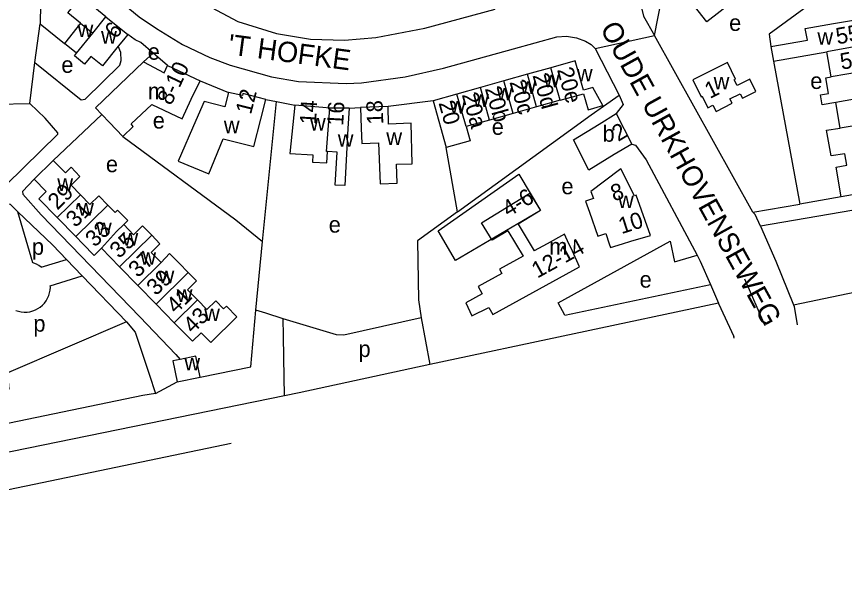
# Model space of a CAD drawing. Extents: x 162883 to 165538, y 383986 to 385172.
# Drawn here: x 164085 to 164288.3, y 384167.4 to 384305.7 of the extents above; entities that cross this region are included whole.
import ezdxf

# ---------------------------------------------------------------- set-up
doc = ezdxf.new("R2010")
doc.units = 0
for name, color, linetype in [('BLT_Basislijn', 7, 'Continuous'), ('BLT_Bebouwing', 7, 'Continuous'), ('BLT_Centroide', 7, 'Continuous'), ('BLT_Huisnummer', 7, 'Continuous'), ('BLT_Huisnummer_ tussenligend', 7, 'Continuous'), ('BLT_Huisnummer_reeks', 7, 'Continuous'), ('BLT_Huisnummer_zonder_bebouwing', 7, 'Continuous'), ('BLT_Onderverdeling_panden', 7, 'Continuous'), ('BLT_Plantopo', 7, 'Continuous'), ('BLT_Spoorlijn', 7, 'Continuous'), ('BLT_Straatnaam', 7, 'Continuous'), ('BLT_Vlakafsluiter', 7, 'Continuous')]:
    doc.layers.add(name, color=color, linetype=linetype)

msp = doc.modelspace()

# ---------------------------------------------------------------- linework, layer by layer
at = {"layer": 'BLT_Basislijn'}
for p, q in [((164106.92, 384305.67), (164100.86, 384310.64)), ((164227.04, 384297.9), (164232.93, 384286.41)), ((164116.19, 384294.57), (164118.57, 384296.7)), ((164122.09, 384293.71), (164118.57, 384296.7)), ((164088.28, 384284.4), (164089.52, 384294.46)), ((164270.83, 384294.78), (164277.3, 384259.69)), ((164130.06, 384289.94), (164137.05, 384287.05)), ((164145.39, 384250.53), (164148.81, 384284.87)), ((164146.25, 384285.35), (164148.81, 384284.87)), ((164148.81, 384284.87), (164153.33, 384284.01)), ((164187.26, 384285.05), (164176.21, 384283.66)), ((164228.98, 384283.9), (164229.11, 384283.72)), ((164166.66, 384283.26), (164169.47, 384283.4)), ((164193.24, 384257.84), (164190.48, 384273.56)), ((164287.5, 384261.53), (164277.3, 384259.69)), ((164265.79, 384257.69), (164277.3, 384259.69)), ((164085.28, 384257.93), (164088.92, 384245.35)), ((164143.72, 384233.7), (164145.39, 384250.53)), ((164217.96, 384235.51), (164245.48, 384250.58)), ((164091.06, 384244.2), (164097.26, 384246.14)), ((164101.13, 384242.11), (164097.26, 384246.14)), ((164093.3, 384239.66), (164101.13, 384242.11)), ((164111.98, 384230.83), (164101.13, 384242.11)), ((164263.74, 384241.37), (164268.73, 384229.94)), ((164219.62, 384232.49), (164255.36, 384240.01)), ((164255.36, 384240.01), (164257.34, 384235.42)), ((164257.34, 384235.42), (164186.45, 384220.4)), ((164219.62, 384232.49), (164217.96, 384235.51)), ((164257.34, 384235.42), (164257.38, 384235.32)), ((164257.38, 384235.32), (164261.11, 384227.25)), ((164146.18, 384232.94), (164143.72, 384233.7)), ((164150.5, 384231.6), (164146.18, 384232.94)), ((164115.27, 384232.08), (164124.08, 384222.79)), ((164150.57, 384227.48), (164150.5, 384231.6)), ((164184.38, 384231.82), (164186.45, 384220.4)), ((164150.67, 384221.99), (164150.57, 384227.48)), ((164261.22, 384226.85), (164261.11, 384227.25)), ((164124.08, 384222.79), (164125.18, 384221.63)), ((164150.83, 384212.71), (164150.67, 384221.99)), ((164186.45, 384220.4), (164154.38, 384213.43)), ((164117.54, 384218), (164119.14, 384213.22)), ((164119.14, 384213.22), (164124.48, 384216.09)), ((164150.83, 384212.71), (163969.22, 384175.66)), ((164119.14, 384213.22), (164116.02, 384212.73)), ((164154.38, 384213.43), (164150.83, 384212.71))]:
    msp.add_line(p, q, dxfattribs=at)
for points in [[(164300.18, 384395.02), (164295.59, 384393.9), (164294.19, 384393.19), (164293.14, 384391.74), (164290.67, 384383.96), (164285.39, 384371.56), (164279.22, 384361.24), (164270.12, 384349.98), (164261.4, 384340.32), (164243.74, 384320.55), (164240.78, 384317.34), (164238.38, 384313.16), (164237.93, 384309.92), (164238.95, 384305.82), (164241.62, 384301.03)], [(164241.62, 384301.03), (164244.24, 384314.47), (164264.79, 384333.93), (164268.2, 384336.97), (164268.52, 384337.22)], [(164090.13, 384329.25), (164104.56, 384315.21), (164110.51, 384309.41), (164115.15, 384305.64), (164119.37, 384302.75), (164125.75, 384298.85), (164132.5, 384295.63), (164137.45, 384293.75), (164147.6, 384290.92), (164154.24, 384289.8), (164165.92, 384289.31), (164169.7, 384289.49), (164180.44, 384290.95), (164189.84, 384293.02), (164207.02, 384297.8), (164217.62, 384300.75), (164220.05, 384300.9), (164222.45, 384300.52), (164224.73, 384299.68), (164226.1, 384298.88), (164227.04, 384297.9)], [(164122.73, 384313.37), (164139.36, 384304.46), (164148.85, 384301.52), (164157.22, 384300.19), (164165.56, 384299.88), (164173.22, 384300.54), (164185.25, 384302.84), (164202.51, 384307.56)], [(164286.77, 384313.86), (164269.82, 384301.39), (164270.2, 384298.36)], [(164089.52, 384294.46), (164090.81, 384303.95)], [(164118.57, 384296.7), (164115.49, 384299.31), (164114.11, 384300), (164112.32, 384301.34)], [(164265.79, 384257.69), (164241.62, 384301.03)], [(164089.52, 384294.46), (164100.84, 384285.29), (164101.86, 384285.45), (164110.41, 384293.77), (164110.72, 384294.94), (164110.6, 384296.92), (164109.99, 384298.43)], [(164537.04, 384298.36), (164444.4, 384281.69), (164443.92, 384281.32), (164443.78, 384279.5), (164414.83, 384274.17), (164413.46, 384274.09), (164412.69, 384277.13), (164412.28, 384277.16), (164358.24, 384267.65), (164355.83, 384267.19), (164355.01, 384265.8), (164304.07, 384256.84), (164302.9, 384256.99), (164302.04, 384260.09), (164301.53, 384260.09), (164267.64, 384254.3)], [(164229.11, 384283.72), (164232.93, 384286.41)], [(164232.93, 384286.41), (164233.96, 384284.12), (164232.26, 384281.94)], [(164061.09, 384244.88), (164062.5, 384245.17), (164065.53, 384247.95), (164095.17, 384276.86), (164095.17, 384277.18), (164092.06, 384280.8), (164088.28, 384284.4)], [(164063.93, 384283.89), (164088.28, 384284.4)], [(164193.24, 384257.84), (164226.1, 384281.59), (164229.11, 384283.72)], [(164105.92, 384281.72), (164094.03, 384270.44)], [(164111.11, 384276.28), (164138.84, 384255.85), (164145.39, 384250.53)], [(164236.06, 384274.4), (164236.95, 384274.14), (164239.55, 384270.6), (164252.11, 384247.18)], [(164089.3, 384265.81), (164086.5, 384262.83), (164086.57, 384262.17), (164091.1, 384257.07), (164115.27, 384232.08)], [(164085.28, 384257.93), (164083.53, 384259.61), (164083.1, 384259.67), (164080.34, 384257.01)], [(164097.26, 384246.14), (164093.89, 384249.64), (164085.28, 384257.93)], [(164193.24, 384257.84), (164183.45, 384250.66), (164183.73, 384236.23), (164184.38, 384231.82)], [(164267.64, 384254.3), (164266.32, 384257.12), (164265.79, 384257.69)], [(164267.64, 384254.3), (164271.43, 384245.69), (164275.8, 384234.96)], [(164245.48, 384250.58), (164246.54, 384245.55), (164252.11, 384247.18)], [(164252.11, 384247.18), (164252.88, 384245.74), (164255.36, 384240.01)], [(164275.8, 384234.96), (164298.55, 384239.75), (164300.69, 384243.25), (164327.24, 384248.79)], [(164091.06, 384244.2), (164090.49, 384244.61), (164089.88, 384244.97), (164089.24, 384245.25), (164088.92, 384245.35)], [(164084.83, 384233.62), (164085.5, 384233.41), (164086.19, 384233.26), (164086.9, 384233.2), (164087.6, 384233.22), (164088.3, 384233.32), (164088.98, 384233.49), (164089.64, 384233.74), (164090.26, 384234.07), (164090.85, 384234.46), (164091.39, 384234.92), (164091.87, 384235.43), (164092.29, 384236), (164092.64, 384236.61), (164092.92, 384237.26), (164093.13, 384237.93), (164093.26, 384238.62), (164093.31, 384239.33), (164093.3, 384239.66)], [(164275.8, 384234.96), (164275.89, 384234.62), (164276.69, 384230.09)], [(164130.1, 384217.27), (164142.51, 384219.77), (164143.72, 384233.7)], [(164111.98, 384230.83), (164083.06, 384218.41), (164082.81, 384218.06), (164083.09, 384214.28), (164082.86, 384214.12), (164071.11, 384211.55)], [(164111.98, 384230.83), (164114.1, 384228.32), (164117.54, 384218)], [(164184.38, 384231.82), (164165.35, 384227.52), (164163.59, 384227.68), (164150.5, 384231.6)], [(164116.02, 384212.73), (163993.66, 384187.45), (163993.19, 384187.45), (163960.99, 384219.5)]]:
    msp.add_lwpolyline(points, dxfattribs=at)
at = {"layer": 'BLT_Bebouwing'}
for p, q in [((164106.92, 384305.67), (164112.32, 384301.34)), ((164270.2, 384298.36), (164270.83, 384294.78)), ((164270.83, 384294.78), (164283.93, 384297.09)), ((164285.02, 384290.91), (164283.93, 384297.09)), ((164122.09, 384293.71), (164130.06, 384289.94)), ((164216.21, 384293.16), (164210.44, 384291.54)), ((164204.67, 384289.93), (164198.9, 384288.31)), ((164210.44, 384291.54), (164204.67, 384289.93)), ((164198.9, 384288.31), (164193.12, 384286.7)), ((164137.05, 384287.05), (164136.15, 384283.55)), ((164193.12, 384286.7), (164187.26, 384285.05)), ((164176.21, 384283.66), (164169.47, 384283.4)), ((164218.45, 384285.18), (164212.68, 384283.56)), ((164287.25, 384278.33), (164286.14, 384284.62)), ((164206.9, 384281.95), (164201.13, 384280.33)), ((164212.68, 384283.56), (164206.9, 384281.95)), ((164232.26, 384281.94), (164236.06, 384274.4)), ((164201.13, 384280.33), (164195.36, 384278.72)), ((164297.47, 384263.31), (164287.5, 384261.53)), ((164099.53, 384251.76), (164095.01, 384256.39)), ((164205.59, 384253.18), (164209.37, 384246.92)), ((164208.13, 384254.77), (164212.07, 384248.25)), ((164110.31, 384244.32), (164105.84, 384248.89)), ((164114.79, 384239.76), (164110.31, 384244.32)), ((164119.26, 384235.19), (164114.79, 384239.76)), ((164123.74, 384230.62), (164119.26, 384235.19)), ((164124.48, 384216.09), (164130.1, 384217.27))]:
    msp.add_line(p, q, dxfattribs=at)
for points in [[(164277.83, 384325.11), (164269.13, 384318.33), (164271.02, 384315.9), (164265.69, 384311.75), (164265.02, 384312.62), (164261.77, 384310.1), (164254.48, 384304.42), (164251.46, 384308.28), (164262.09, 384316.57), (164258.05, 384321.75), (164271.95, 384332.65)], [(164091.09, 384318.57), (164090.99, 384313.57), (164090.81, 384303.95)], [(164100.71, 384304.09), (164097.58, 384306.63), (164100.86, 384310.64)], [(164090.81, 384303.95), (164096.82, 384299.08)], [(164100.71, 384304.09), (164103.71, 384301.67)], [(164103.71, 384301.67), (164106.92, 384305.67)], [(164270.2, 384298.36), (164279.16, 384299.94), (164278.66, 384302.78), (164285.54, 384303.97), (164290.46, 384304.84), (164290.6, 384304.05), (164291.7, 384304.25), (164292.27, 384301.07), (164291.16, 384300.88), (164291.59, 384298.45)], [(164112.32, 384301.34), (164111.25, 384300), (164109.99, 384298.43)], [(164099.74, 384296.72), (164096.82, 384299.08)], [(164109.99, 384298.43), (164106.12, 384293.61), (164103.23, 384295.93), (164101.73, 384294.05), (164099.22, 384296.07), (164099.74, 384296.72)], [(164116.19, 384294.57), (164104.4, 384283.32), (164105.92, 384281.72)], [(164116.19, 384294.57), (164121.22, 384291.88), (164122.09, 384293.71)], [(164228.98, 384283.9), (164226.51, 384288.3), (164224.17, 384287.65), (164222.16, 384294.83), (164216.21, 384293.16)], [(164260.72, 384284.43), (164260.17, 384285.54), (164262.66, 384286.78), (164263.21, 384285.67), (164266.54, 384287.33), (164265.03, 384290.37), (164261.89, 384288.81), (164261.2, 384290.2), (164261.56, 384290.38), (164259.56, 384294.4), (164255.48, 384292.37), (164251.01, 384290.15), (164253.06, 384286.03), (164253.35, 384286.18), (164254.75, 384283.35), (164255.99, 384283.97), (164256.75, 384282.45), (164260.72, 384284.43)], [(164111.11, 384276.28), (164113.66, 384278.71), (164113.19, 384279.39), (164118.19, 384284.16), (164125.65, 384280.63), (164127.92, 384285.42), (164130.06, 384289.94)], [(164286.14, 384284.62), (164282.78, 384284.07), (164282.36, 384286.49), (164284.37, 384286.85), (164283.69, 384290.64), (164285.02, 384290.91)], [(164146.25, 384285.35), (164140.6, 384286.8), (164140.49, 384286.37), (164137.05, 384287.05)], [(164218.45, 384285.18), (164224.22, 384286.79), (164225.31, 384282.87), (164228.98, 384283.9)], [(164136.15, 384283.55), (164131.05, 384284.85), (164129.04, 384280.2), (164124.72, 384270.24), (164132.19, 384267.15), (164135.76, 384275.75)], [(164135.76, 384275.75), (164143.3, 384273.82), (164145.01, 384280.51), (164146.25, 384285.35)], [(164153.33, 384284.01), (164152.13, 384272.1), (164157.76, 384271.78), (164157.66, 384270.01), (164161.23, 384269.81), (164161.38, 384272.6)], [(164161.96, 384283.22), (164160.25, 384283.42), (164153.33, 384284.01)], [(164169.47, 384283.4), (164169.66, 384278.36), (164169.81, 384274.59), (164173.91, 384274.75), (164174.31, 384264.68), (164178.42, 384264.85), (164178.33, 384269.52), (164182.13, 384269.58), (164181.89, 384279.53), (164176.37, 384279.32), (164176.21, 384283.66)], [(164187.26, 384285.05), (164190.48, 384273.56)], [(164105.92, 384281.72), (164107.85, 384279.7), (164111.11, 384276.28)], [(164166.66, 384283.26), (164166.38, 384278.24), (164165.59, 384264.26), (164163.26, 384264.39), (164163.71, 384272.47), (164161.38, 384272.6)], [(164166.66, 384283.26), (164166.45, 384283.24), (164161.96, 384283.22)], [(164236.06, 384274.4), (164231.77, 384271.84), (164225.48, 384268.07), (164221.77, 384275.46), (164228.01, 384279.3), (164232.26, 384281.94)], [(164195.36, 384278.72), (164196.35, 384275.2), (164190.48, 384273.56)], [(164288.36, 384272.04), (164285, 384271.51), (164283.89, 384277.81), (164287.25, 384278.33)], [(164287.5, 384261.53), (164286.22, 384268.78), (164288.86, 384269.24), (164288.61, 384270.67), (164288.36, 384272.04)], [(164089.3, 384265.81), (164094.03, 384270.44)], [(164094.03, 384270.44), (164097.01, 384267.39), (164098.39, 384268.74), (164100.57, 384266.51), (164098.39, 384264.39), (164100.74, 384261.99)], [(164225.65, 384257.75), (164227.74, 384251.83), (164229.65, 384252.5), (164230.53, 384250), (164230.86, 384249.06), (164233.75, 384250), (164235.85, 384250.62), (164240.65, 384252.04), (164237.17, 384261.91), (164236.73, 384261.76), (164233.35, 384268.32), (164229.36, 384265.31), (164226.04, 384262.81), (164226.65, 384261.09), (164224.72, 384260.41), (164225.65, 384257.75)], [(164095.01, 384256.39), (164090.49, 384261.02), (164092.27, 384262.76), (164089.3, 384265.81)], [(164100.74, 384261.99), (164103.04, 384259.63), (164105.21, 384261.75), (164107.43, 384259.48)], [(164205.59, 384253.18), (164201.76, 384250.83), (164199.13, 384255.1), (164211.01, 384262.41), (164213.62, 384258.15), (164208.13, 384254.77)], [(164107.43, 384259.48), (164109.19, 384257.68), (164109.77, 384258.25), (164112.3, 384255.67), (164111.32, 384254.7)], [(164111.32, 384254.7), (164113.75, 384252.21), (164115.96, 384254.38), (164118.21, 384252.06)], [(164105.84, 384248.89), (164104.05, 384247.13), (164101.25, 384250), (164099.53, 384251.76)], [(164118.21, 384252.06), (164120.21, 384250), (164118.04, 384247.85), (164120.49, 384245.35)], [(164221.14, 384248.88), (164220.62, 384250), (164219.56, 384252.3), (164215.28, 384250), (164212.07, 384248.25)], [(164120.49, 384245.35), (164122.59, 384247.58), (164124.94, 384245.18), (164127.15, 384242.92)], [(164209.37, 384246.92), (164203.55, 384243.72), (164204.12, 384242.68), (164198.34, 384239.5), (164199.33, 384237.71), (164195.31, 384235.49), (164196.82, 384232.27), (164200.98, 384234.35), (164201.93, 384232.62), (164223.23, 384244.33), (164221.14, 384248.88)], [(164127.15, 384242.92), (164129.18, 384240.86), (164126.99, 384238.71), (164129.44, 384236.21)], [(164129.44, 384236.21), (164131.77, 384233.84), (164133.93, 384235.96), (164135.86, 384233.99), (164136.58, 384234.7), (164139.13, 384232.09), (164132.7, 384225.79), (164130.37, 384228.17), (164128.21, 384226.05), (164123.74, 384230.62)], [(164125.18, 384221.63), (164123.4, 384221.25), (164123.4, 384221.25), (164124.48, 384216.09)], [(164130.1, 384217.27), (164129.01, 384222.43), (164125.18, 384221.63)]]:
    msp.add_lwpolyline(points, dxfattribs=at)
at = {"layer": 'BLT_Onderverdeling_panden'}
for p, q in [((164100.71, 384304.09), (164096.82, 384299.08)), ((164099.74, 384296.72), (164103.71, 384301.67)), ((164291.59, 384298.45), (164283.93, 384297.09)), ((164218.45, 384285.18), (164216.21, 384293.16)), ((164292.68, 384292.27), (164285.02, 384290.91)), ((164206.9, 384281.95), (164204.67, 384289.93)), ((164212.68, 384283.56), (164210.44, 384291.54)), ((164201.13, 384280.33), (164198.9, 384288.31)), ((164195.36, 384278.72), (164193.12, 384286.7)), ((164293.8, 384285.98), (164286.14, 384284.62)), ((164294.91, 384279.69), (164287.25, 384278.33)), ((164095.01, 384256.39), (164100.74, 384261.99)), ((164099.53, 384251.76), (164107.43, 384259.48)), ((164110.31, 384244.32), (164118.21, 384252.06)), ((164114.79, 384239.76), (164120.49, 384245.35)), ((164119.26, 384235.19), (164127.15, 384242.92)), ((164123.74, 384230.62), (164129.44, 384236.21))]:
    msp.add_line(p, q, dxfattribs=at)
for points in [[(164161.38, 384272.6), (164161.07, 384272.62), (164161.96, 384283.22)], [(164111.32, 384254.7), (164109.57, 384252.99), (164105.84, 384248.89)]]:
    msp.add_lwpolyline(points, dxfattribs=at)
at = {"layer": 'BLT_Plantopo'}
msp.add_lwpolyline([(164188.51, 384253.12), (164208.35, 384267.06), (164213.62, 384258.15), (164192.81, 384245.84)], close=True, dxfattribs=at)
at = {"layer": 'BLT_Spoorlijn'}
msp.add_lwpolyline([(164137.67, 384200.96), (163976.02, 384167.4)], dxfattribs=at)
at = {"layer": 'BLT_Vlakafsluiter'}
msp.add_line((164227.04, 384297.9), (164241.62, 384301.03), dxfattribs=at)

# ---------------------------------------------------------------- texts
at = {"layer": 'BLT_Centroide'}
for s, p in [('e', (164259.96, 384302.19)), ('w', (164100, 384300.67)), ('w', (164105.77, 384299.06)), ('w', (164281.62, 384298.79)), ('e', (164117.23, 384295.11)), ('e', (164096.02, 384291.9)), ('w', (164222.59, 384289.81)), ('w', (164208.67, 384286.75)), ('w', (164214.44, 384288.36)), ('w', (164256.16, 384287.84)), ('e', (164279.88, 384287.95)), ('m', (164117.27, 384285.44)), ('w', (164202.91, 384285.12)), ('w', (164197.12, 384283.52)), ('w', (164191.36, 384281.89)), ('e', (164118.46, 384278.24)), ('w', (164135.91, 384277.09)), ('w', (164157.05, 384277.75)), ('e', (164201.68, 384276.7)), ('b', (164228.88, 384275)), ('w', (164163.88, 384273.78)), ('w', (164175.8, 384274.2)), ('e', (164106.95, 384267.53)), ('w', (164095.02, 384262.92)), ('e', (164218.79, 384262.12)), ('w', (164232.69, 384258.73)), ('w', (164100.13, 384256.88)), ('w', (164104.52, 384252.11)), ('e', (164161.66, 384252.71)), ('w', (164111.02, 384249.53)), ('p', (164088.79, 384247.28)), ('m', (164215.79, 384247.34)), ('w', (164115.41, 384244.83)), ('w', (164119.88, 384240.28)), ('e', (164237.98, 384239.22)), ('w', (164124.34, 384235.7)), ('w', (164131.07, 384231)), ('p', (164089.15, 384228.42)), ('p', (164168.96, 384222.2)), ('w', (164126.21, 384218.92))]:
    msp.add_text(s, height=4, dxfattribs=at).set_placement(p)
at = {"layer": 'BLT_Huisnummer'}
for s, rotation, p in [('6', 51.2648, (164109.4, 384300.04)), ('55', 10.0314, (164286.52, 384298.87)), ('20e', 285.6396, (164217.67, 384292.69)), ('1', 26.4468, (164255.21, 384285.47)), ('12', 75.6538, (164142.57, 384281.54)), ('20b', 285.6396, (164199.96, 384288.06)), ('14', 86.7629, (164158.52, 384279.14)), ('16', 86.7719, (164165.2, 384278.84)), ('18', 92.2284, (164175.07, 384279.31)), ('20', 285.6376, (164188.58, 384284.54)), ('2', 30.8994, (164232.72, 384274.94)), ('29', 44.3361, (164095.04, 384258.11)), ('33', 44.3361, (164104.24, 384248.96)), ('37', 44.3361, (164114.82, 384241.49)), ('43', 44.3361, (164128.26, 384227.78))]:
    msp.add_text(s, height=4, rotation=rotation, dxfattribs=at).set_placement(p)
at = {"layer": 'BLT_Huisnummer_ tussenligend'}
for s, rotation, p in [('53', 10.0314, (164287.56, 384292.66)), ('20d', 285.6369, (164211.66, 384291.28)), ('20c', 285.6396, (164206.01, 384289.67)), ('20a', 285.6396, (164194.29, 384286.56)), ('31', 44.3361, (164099.47, 384253.78)), ('35', 44.3361, (164110.23, 384246.19)), ('39', 44.3361, (164119.26, 384237.06)), ('41', 44.3361, (164124.13, 384232.61))]:
    msp.add_text(s, height=4, rotation=rotation, dxfattribs=at).set_placement(p)
at = {"layer": 'BLT_Huisnummer_reeks'}
for s, rotation, p in [('8-10', 64.6713, (164122.96, 384283.72)), ('8', 17.8994, (164231.63, 384260.34)), ('10', 17.8994, (164233.54, 384252.32)), ('12-14', 28.8147, (164212.87, 384241.42))]:
    msp.add_text(s, height=4, rotation=rotation, dxfattribs=at).set_placement(p)
at = {"layer": 'BLT_Huisnummer_zonder_bebouwing'}
msp.add_text('4-6', height=4, rotation=30.8147, dxfattribs=at).set_placement((164205.76, 384256.41))
at = {"layer": 'BLT_Straatnaam'}
for s, rotation, p in [('OUDE URKHOVENSEWEG', 298.8702, (164228.17, 384302.81)), ("'T HOFKE", 352.4228, (164136.72, 384296.48))]:
    msp.add_text(s, height=5, rotation=rotation, dxfattribs=at).set_placement(p)

doc.saveas('drawing.dxf')
